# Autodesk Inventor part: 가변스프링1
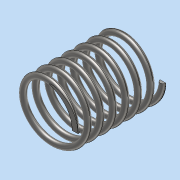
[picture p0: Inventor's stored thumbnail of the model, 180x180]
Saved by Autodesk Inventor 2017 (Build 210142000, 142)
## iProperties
Part Number: 가변스프링1
Material: 스테인레스 스틸
Document SubType Name: Modeling
Designer: MRC
Density: 8 g/cm^3
Appearance: 반연마
Mass: 10.9002 g
Surface Area: 27.5826 cm^2
Volume: 1.36253 cm^3
Author: MRC
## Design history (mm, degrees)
sketch "스케치1"
  geometry: L1 (0, 0)-(10, 0); L2 (10, 0)-(10, 30.208); L3 (10, 30.208)-(0, 30.208); L4 (0, 30.208)-(0, 0); C1 r 1 at (10, 0)
  constraints: 8 end point, 2 parallel, 1 centre point, 1 coincident, 1 horizontal, 1 perpendicular
  dimensions: "d0" = 30.20829 distance between parallel lines of L1 L3 (derived); "d1" = 20 diameter of L2 L4; "d2" = 2 diameter of C1
feature "코일1" sketch "스케치1" pitch "d3" = 10; turns "d5" = 7; dims "d4" = 30.20829 (= d0), "d6" = 0, angle "d7" = 90 deg, angle "d8" = 90 deg, "d9" = 0, "d10" = 0
sketch "스케치2"
  geometry: L1 (0, -17.9)-(30.208, -17.9); L2 (30.208, -17.9)-(30.208, 17.9); L3 (30.208, 17.9)-(0, 17.9); L4 (0, 17.9)-(0, -17.9); 4 further points
  constraints: 8 end point, 2 coincident, 2 midpoint, 2 parallel, 1 horizontal, 1 perpendicular
  dimensions: "d11" = 35.80033 distance between parallel lines of L1 L3
extrude "돌출1" sketch "스케치2" stored distance "d12" = 50; taper "d13" = 0 deg
node "솔리드1"
